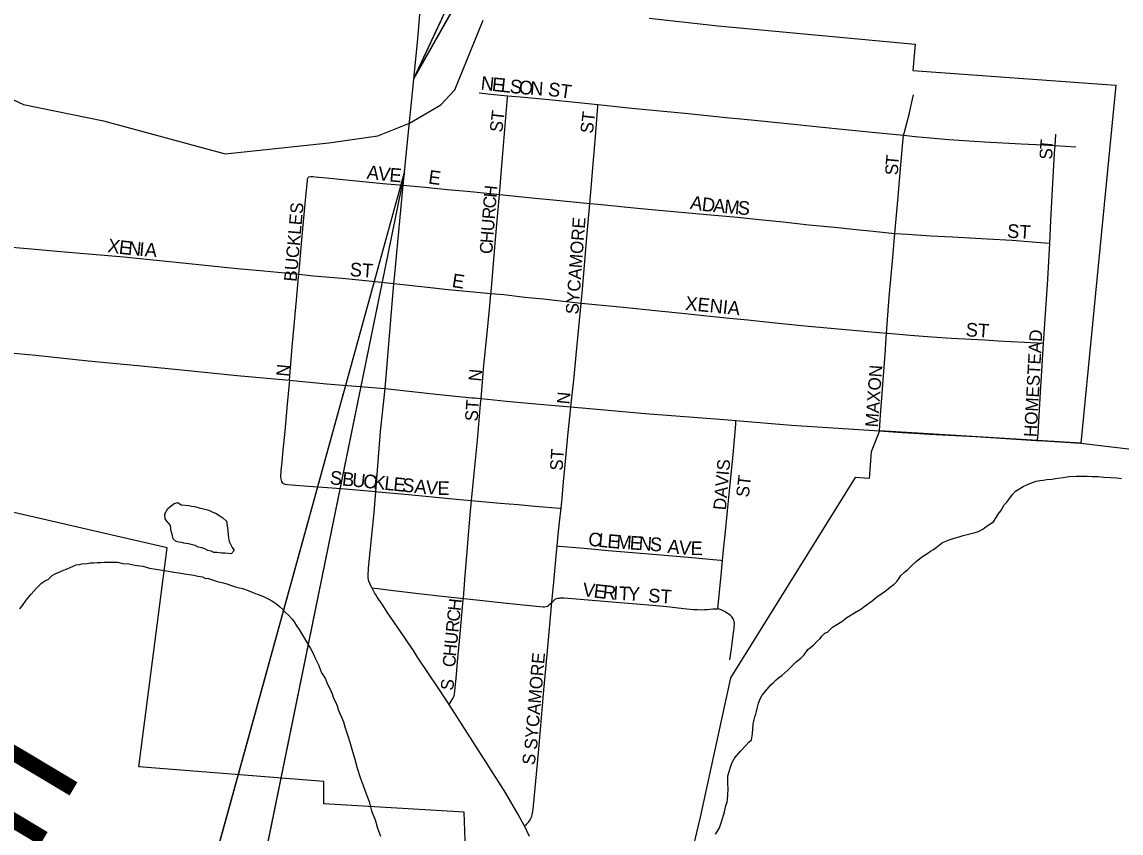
# Model space of a CAD drawing. Extents: x -13.9 to 69.1, y -25.2 to 26.1.
# Drawn here: x 3.981 to 4.71, y 17.455 to 17.993 of the extents above; entities that cross this region are included whole.
import ezdxf

# ---------------------------------------------------------------- set-up
doc = ezdxf.new("R2010")
doc.units = 0
for name, color, linetype in [('GM_X_City_Street', 7, 'Continuous'), ('GM_X_City_Street_Text', 7, 'Continuous'), ('GM_X_Corporation', 7, 'Continuous'), ('GM_X_Major_River', 7, 'Continuous'), ('GM_X_Minor_Lake', 7, 'Continuous'), ('GM_X_Minor_River', 7, 'Continuous'), ('GM_X_Minor_River_Text', 7, 'Continuous'), ('GM_X_State_Route', 7, 'Continuous'), ('SH_Text', 7, 'Continuous')]:
    doc.layers.add(name, color=color, linetype=linetype)

msp = doc.modelspace()

# ---------------------------------------------------------------- linework, layer by layer
at = {"layer": 'GM_X_City_Street'}
for points in [[(4.28452, 17.94603), (4.29432, 17.94511), (4.30348, 17.94424)], [(4.29797, 17.87876), (4.29973, 17.9005), (4.30339, 17.94304), (4.30348, 17.94424)], [(4.30348, 17.94424), (4.3145, 17.9432), (4.3354, 17.94119), (4.36326, 17.93837)], [(4.56601, 17.91796), (4.56654, 17.92013), (4.56819, 17.92613), (4.56967, 17.93173), (4.57085, 17.93704), (4.57251, 17.94487)], [(4.35791, 17.87281), (4.35887, 17.88294), (4.3602, 17.89913), (4.36166, 17.91696), (4.36318, 17.93723), (4.36326, 17.93837)], [(4.36326, 17.93837), (4.3859, 17.93607), (4.42091, 17.93272), (4.45053, 17.92965), (4.45809, 17.92889), (4.46946, 17.92778), (4.49323, 17.92528), (4.50999, 17.92352), (4.52746, 17.92186), (4.54296, 17.92038), (4.56601, 17.91796)], [(4.56031, 17.85291), (4.56213, 17.87471), (4.56417, 17.89849), (4.56544, 17.91328), (4.56601, 17.91796)], [(4.56601, 17.91796), (4.57367, 17.91716), (4.59601, 17.91514), (4.61974, 17.91373), (4.64409, 17.91238), (4.65881, 17.91156), (4.66644, 17.91113)], [(4.66644, 17.91113), (4.66669, 17.91455), (4.66699, 17.91865)], [(4.6629, 17.84642), (4.66369, 17.8615), (4.66458, 17.87814), (4.66608, 17.90624), (4.66644, 17.91113)], [(4.66644, 17.91113), (4.68017, 17.91037)], [(4.16497, 17.82582), (4.16559, 17.83265), (4.16682, 17.84626), (4.16785, 17.85831), (4.16994, 17.87968), (4.17067, 17.88768), (4.17082, 17.8891), (4.17101, 17.8896), (4.17118, 17.88997), (4.17166, 17.89036), (4.1729, 17.89059), (4.17436, 17.89063), (4.17586, 17.89051), (4.18332, 17.88978), (4.19854, 17.88828), (4.21405, 17.88675), (4.22073, 17.88611), (4.22885, 17.88533), (4.23425, 17.88481)], [(4.23425, 17.88481), (4.24876, 17.88363), (4.26338, 17.88212), (4.27658, 17.88083), (4.29412, 17.87915), (4.29797, 17.87876)], [(4.29242, 17.81314), (4.29249, 17.81401), (4.29429, 17.83554), (4.29543, 17.84878), (4.29695, 17.86625), (4.29797, 17.87876)], [(4.29797, 17.87876), (4.32161, 17.87639), (4.33358, 17.87521), (4.35791, 17.87281)], [(4.35232, 17.80677), (4.35285, 17.81324), (4.35615, 17.85288), (4.35742, 17.86766), (4.35791, 17.87281)], [(4.35791, 17.87281), (4.36332, 17.87228), (4.39186, 17.86947), (4.43302, 17.86576), (4.45598, 17.86369), (4.4703, 17.86218), (4.48611, 17.86051), (4.5032, 17.85871), (4.52011, 17.85702), (4.53453, 17.85555), (4.54592, 17.8544), (4.56031, 17.85291)], [(4.55478, 17.78675), (4.55653, 17.81075), (4.55878, 17.83443), (4.56031, 17.85291)], [(4.56031, 17.85291), (4.56868, 17.85236), (4.58413, 17.85142), (4.59837, 17.85062), (4.62154, 17.84933), (4.63799, 17.84841), (4.65385, 17.84701), (4.6629, 17.84642)], [(3.96097, 17.84498), (3.98006, 17.84336), (3.99255, 17.84228), (4.00966, 17.84081), (4.04898, 17.83743), (4.08147, 17.83411), (4.1242, 17.82975), (4.14183, 17.82805), (4.16497, 17.82582)], [(4.65891, 17.78016), (4.66016, 17.7995), (4.66164, 17.82247), (4.6629, 17.84642)], [(4.15879, 17.75552), (4.16066, 17.77774), (4.16221, 17.79422), (4.16263, 17.79946), (4.16342, 17.80876), (4.1648, 17.82391), (4.16497, 17.82582)], [(4.16497, 17.82582), (4.17476, 17.82488), (4.19383, 17.82315), (4.21147, 17.82152), (4.22809, 17.81972)], [(4.22809, 17.81972), (4.25037, 17.81719), (4.26393, 17.81569), (4.27102, 17.81511), (4.29242, 17.81314)], [(4.28587, 17.74337), (4.28773, 17.76547), (4.2896, 17.78458), (4.29159, 17.80492), (4.29242, 17.81314)], [(4.29242, 17.81314), (4.30097, 17.81235), (4.31489, 17.81074), (4.32699, 17.80946), (4.35232, 17.80677)], [(4.34536, 17.73786), (4.34751, 17.75787), (4.34891, 17.77215), (4.35025, 17.78595), (4.35232, 17.80677)], [(4.35232, 17.80677), (4.36395, 17.80554), (4.38014, 17.80399), (4.4015, 17.8019), (4.42113, 17.79987), (4.43563, 17.79836), (4.45051, 17.79682), (4.4628, 17.79554), (4.47877, 17.79388), (4.50053, 17.79162), (4.53738, 17.78827), (4.55478, 17.78675)], [(4.55009, 17.72192), (4.55074, 17.73251), (4.55377, 17.77283), (4.55478, 17.78675)], [(4.55478, 17.78675), (4.55553, 17.78668), (4.5704, 17.7854), (4.5847, 17.78426), (4.5979, 17.78351), (4.61994, 17.78239), (4.62875, 17.78173), (4.65468, 17.78038), (4.65891, 17.78016)], [(3.95538, 17.77564), (3.97146, 17.77403), (3.99066, 17.77209), (4.02531, 17.76854), (4.05827, 17.76524), (4.09169, 17.76208), (4.12413, 17.75877), (4.15879, 17.75552)], [(4.65485, 17.71566), (4.65516, 17.72058), (4.65692, 17.74772), (4.65793, 17.76516), (4.65891, 17.78016)], [(4.15879, 17.75552), (4.15859, 17.75349), (4.15729, 17.73962), (4.15565, 17.72177), (4.15441, 17.7092), (4.15366, 17.70153), (4.15316, 17.69561), (4.15294, 17.69146), (4.15302, 17.69011), (4.15317, 17.6892), (4.15353, 17.68842), (4.15397, 17.68783), (4.15452, 17.68728), (4.15518, 17.68689), (4.15602, 17.68665), (4.15745, 17.68646), (4.16272, 17.68606), (4.17146, 17.68542), (4.18083, 17.68474), (4.19311, 17.68386), (4.21606, 17.68175)], [(4.15879, 17.75552), (4.18329, 17.75323), (4.22219, 17.75004)], [(4.27948, 17.67578), (4.28129, 17.69379), (4.2835, 17.71586), (4.28555, 17.73971), (4.28587, 17.74337)], [(4.33887, 17.67068), (4.33961, 17.67742), (4.34056, 17.68812), (4.342, 17.70407), (4.34332, 17.71872), (4.3451, 17.73546), (4.34536, 17.73786)], [(4.44597, 17.63606), (4.44693, 17.64524), (4.44773, 17.65313), (4.44925, 17.66907), (4.45071, 17.68442), (4.45299, 17.70604), (4.45468, 17.72634), (4.45488, 17.7288)], [(4.21606, 17.68175), (4.2177, 17.6816), (4.23311, 17.68034), (4.25584, 17.67804), (4.27178, 17.67643), (4.27948, 17.67578)], [(4.27414, 17.61081), (4.27518, 17.62351), (4.27868, 17.66624), (4.27948, 17.67578)], [(4.27948, 17.67578), (4.28645, 17.67517), (4.29856, 17.67413), (4.3104, 17.67312), (4.32146, 17.67218), (4.33813, 17.67076), (4.33887, 17.67068)], [(4.33634, 17.64573), (4.33704, 17.65298), (4.33786, 17.66149), (4.33887, 17.67068)], [(4.33269, 17.60831), (4.3331, 17.6128), (4.33402, 17.62165), (4.33568, 17.63888), (4.33634, 17.64573)], [(4.33634, 17.64573), (4.33773, 17.6456), (4.35415, 17.64416), (4.37007, 17.64277), (4.39985, 17.64016), (4.42315, 17.63816), (4.4447, 17.63618), (4.44597, 17.63606)], [(4.4428, 17.6041), (4.44496, 17.62636), (4.44597, 17.63606)], [(4.21339, 17.618), (4.21745, 17.61748), (4.22786, 17.61618), (4.2443, 17.61424), (4.26001, 17.61238), (4.27414, 17.61081)], [(4.26458, 17.54047), (4.26609, 17.5428), (4.26719, 17.5445), (4.26765, 17.54552), (4.26798, 17.54663), (4.26812, 17.54761), (4.26927, 17.55788), (4.27027, 17.56883), (4.27197, 17.58737), (4.27407, 17.61004), (4.27414, 17.61081)], [(4.27414, 17.61081), (4.28504, 17.60965), (4.29679, 17.60841), (4.31382, 17.60661), (4.32704, 17.60523), (4.32801, 17.60529), (4.32906, 17.60549), (4.32987, 17.60576), (4.33063, 17.6063), (4.3314, 17.60706), (4.33269, 17.6083), (4.33269, 17.60831)], [(4.31456, 17.46016), (4.31587, 17.46132), (4.31728, 17.4626), (4.31808, 17.46366), (4.31857, 17.46449), (4.31912, 17.46563), (4.31941, 17.46646), (4.31971, 17.46732), (4.31993, 17.4685), (4.32011, 17.4696), (4.32038, 17.47132), (4.32063, 17.47341), (4.32222, 17.4897), (4.32384, 17.50844), (4.32539, 17.52641), (4.32734, 17.54772), (4.3298, 17.57613), (4.33269, 17.60831)], [(4.33269, 17.60831), (4.33364, 17.60915), (4.33432, 17.60984), (4.33499, 17.61042), (4.33575, 17.61078), (4.33682, 17.61106), (4.33774, 17.61117), (4.33855, 17.61123), (4.33951, 17.61123), (4.34065, 17.6112), (4.34896, 17.61059), (4.3728, 17.60864), (4.39693, 17.60667), (4.40904, 17.60554), (4.42223, 17.6041), (4.42661, 17.60362), (4.42946, 17.60345), (4.43207, 17.60337), (4.43395, 17.60348), (4.4359, 17.60356), (4.43757, 17.60378), (4.43946, 17.60395), (4.44104, 17.6041), (4.4428, 17.6041)], [(4.45091, 17.57023), (4.45191, 17.57745), (4.45334, 17.58822), (4.45363, 17.59105), (4.45377, 17.59232), (4.45384, 17.59357), (4.45387, 17.59455), (4.45365, 17.59569), (4.45343, 17.59644), (4.45304, 17.59733), (4.45265, 17.59804), (4.4521, 17.59879), (4.4513, 17.59967), (4.45047, 17.60033), (4.44985, 17.60076), (4.44912, 17.60119), (4.44719, 17.60225), (4.4456, 17.60301), (4.44405, 17.60367), (4.4428, 17.6041)]]:
    msp.add_lwpolyline(points, dxfattribs=at)
at = {"layer": 'GM_X_Corporation'}
for points in [[(4.39727, 17.99575), (4.44305, 17.99067), (4.57374, 17.97833), (4.57208, 17.96095), (4.70688, 17.95124), (4.68348, 17.71385), (4.65485, 17.71566), (4.55009, 17.72192), (4.5445, 17.70802), (4.54315, 17.6904), (4.53402, 17.69118), (4.45123, 17.55819), (4.43114, 17.46595), (4.42416, 17.43621)], [(4.27723, 17.39488), (4.27455, 17.46918), (4.18168, 17.47477), (4.18168, 17.48942), (4.05882, 17.49916), (4.0776, 17.64436), (3.89621, 17.68632)]]:
    msp.add_lwpolyline(points, dxfattribs=at)
at = {"layer": 'GM_X_Major_River'}
msp.add_lwpolyline([(3.83078, 17.9959), (3.87742, 17.98798), (3.88715, 17.98632), (3.91888, 17.97364), (3.94781, 17.95447), (3.98252, 17.93846), (4.03549, 17.92749), (4.11619, 17.90574), (4.18499, 17.91296), (4.21738, 17.91771), (4.2384, 17.92597), (4.25916, 17.93823), (4.26844, 17.9482), (4.28713, 17.9943)], dxfattribs=at)
at = {"layer": 'GM_X_Minor_Lake'}
msp.add_lwpolyline([(4.07615, 17.66692), (4.07821, 17.67053), (4.08229, 17.67375), (4.08466, 17.67445), (4.08701, 17.67297), (4.09207, 17.67254), (4.09375, 17.67216), (4.09611, 17.67177), (4.09881, 17.67101), (4.10184, 17.67024), (4.10352, 17.66986), (4.10521, 17.66948), (4.10756, 17.66836), (4.11025, 17.66723), (4.1126, 17.66575), (4.11461, 17.66427), (4.11695, 17.66206), (4.1179, 17.65587), (4.1182, 17.65259), (4.11884, 17.64858), (4.12082, 17.64456), (4.12216, 17.64272), (4.12011, 17.64056), (4.11606, 17.64098), (4.1137, 17.64101), (4.11067, 17.64141), (4.10864, 17.64143), (4.10696, 17.64218), (4.1046, 17.64257), (4.10259, 17.64369), (4.10057, 17.64444), (4.09821, 17.64483), (4.0962, 17.64595), (4.0935, 17.64671), (4.09182, 17.64709), (4.08879, 17.64749), (4.0871, 17.64788), (4.08542, 17.64826), (4.08373, 17.64864), (4.08173, 17.65049), (4.08108, 17.6534), (4.08042, 17.65523), (4.07979, 17.65924), (4.07779, 17.66181), (4.07646, 17.66364), (4.07614, 17.66619), (4.07615, 17.66692), (4.07615, 17.66655)], dxfattribs=at)
at = {"layer": 'GM_X_Minor_River'}
for points in [[(4.6359, 17.67651), (4.63829, 17.67975), (4.64034, 17.68191), (4.64543, 17.68512), (4.64815, 17.68654), (4.65086, 17.6876), (4.65391, 17.68865), (4.65627, 17.68899), (4.65864, 17.68932), (4.661, 17.68966), (4.66438, 17.68998), (4.6681, 17.69066), (4.67182, 17.69098), (4.67587, 17.69166), (4.6806, 17.69197), (4.68432, 17.69192), (4.68769, 17.69188), (4.69107, 17.69184), (4.69478, 17.6918), (4.69883, 17.69138), (4.70321, 17.69097), (4.70726, 17.69092), (4.71063, 17.69051)], [(4.44131, 17.45448), (4.44268, 17.45664), (4.44405, 17.45881), (4.44509, 17.46207), (4.44614, 17.46569), (4.44719, 17.46931), (4.44825, 17.47367), (4.44894, 17.47584), (4.4493, 17.47765), (4.4497, 17.4842), (4.44941, 17.48856), (4.44945, 17.49329), (4.4505, 17.49691), (4.4512, 17.49909), (4.45223, 17.50162), (4.45395, 17.50487), (4.45806, 17.50991), (4.46113, 17.51315), (4.46351, 17.51567), (4.46521, 17.5171), (4.46593, 17.52109), (4.46633, 17.52763), (4.46703, 17.53054), (4.46739, 17.53235), (4.46808, 17.53416), (4.46844, 17.53597), (4.46914, 17.53887), (4.46984, 17.54141), (4.47122, 17.54467), (4.47226, 17.54684), (4.47806, 17.55368), (4.47976, 17.55511), (4.48147, 17.55691), (4.48317, 17.55834), (4.48521, 17.55977), (4.48725, 17.56157), (4.4893, 17.56336), (4.49203, 17.56624), (4.49475, 17.56875), (4.49781, 17.57126), (4.5002, 17.57341), (4.5026, 17.57702), (4.50634, 17.57988), (4.50839, 17.5824), (4.51043, 17.5842), (4.51214, 17.58599), (4.51384, 17.58779), (4.51554, 17.5885), (4.51894, 17.59173), (4.52166, 17.59352), (4.52506, 17.59566), (4.52846, 17.59816), (4.53355, 17.60137), (4.53763, 17.60387), (4.54137, 17.60673), (4.54511, 17.60923), (4.54817, 17.61174), (4.55157, 17.61425), (4.55463, 17.61639), (4.55735, 17.61854), (4.55973, 17.62033), (4.56144, 17.62213), (4.56281, 17.62393), (4.56418, 17.6261), (4.56656, 17.62825), (4.56894, 17.63004), (4.57133, 17.63256), (4.57439, 17.63543), (4.5778, 17.6383), (4.58153, 17.64043), (4.58391, 17.64222), (4.58595, 17.64329), (4.58765, 17.64472), (4.58969, 17.64615), (4.59173, 17.64795), (4.59614, 17.64971), (4.59953, 17.65076), (4.60291, 17.65181), (4.60562, 17.65251), (4.6134, 17.65459), (4.61577, 17.65529), (4.61849, 17.65671), (4.62086, 17.6585), (4.62392, 17.66065), (4.62562, 17.66172), (4.62871, 17.66677), (4.63042, 17.66894), (4.63282, 17.67291), (4.63453, 17.6747), (4.6359, 17.67651)], [(3.98001, 17.60408), (3.98171, 17.60624), (3.98411, 17.60985), (3.98753, 17.6138), (3.99094, 17.61776), (3.99435, 17.621), (3.99707, 17.62278), (3.99876, 17.62349), (4.00149, 17.626), (4.00387, 17.62743), (4.00658, 17.62849), (4.00895, 17.62955), (4.01132, 17.63061), (4.01336, 17.63131), (4.01539, 17.63238), (4.01742, 17.63308), (4.01945, 17.63342), (4.02114, 17.63376), (4.02452, 17.63409), (4.02689, 17.63442), (4.02891, 17.6344), (4.03128, 17.63473), (4.03364, 17.6347), (4.03601, 17.63504), (4.03871, 17.635), (4.04141, 17.63497), (4.04478, 17.63493), (4.04815, 17.63416), (4.0522, 17.63375), (4.05624, 17.63297), (4.06163, 17.63218), (4.06601, 17.63104), (4.07848, 17.62907), (4.08218, 17.6283), (4.08555, 17.62789), (4.08926, 17.62712), (4.09229, 17.62672), (4.09533, 17.62632), (4.09802, 17.62556), (4.10106, 17.62516), (4.10274, 17.62441), (4.1051, 17.62402), (4.10779, 17.62326), (4.11082, 17.62213), (4.11384, 17.62137), (4.11721, 17.6206), (4.12024, 17.61947), (4.1236, 17.61834), (4.12765, 17.61756), (4.13134, 17.61606), (4.13403, 17.61494), (4.1374, 17.61381), (4.14043, 17.61268), (4.14278, 17.61156), (4.14513, 17.61044), (4.14714, 17.60933), (4.14882, 17.60821), (4.1505, 17.6071), (4.15217, 17.60563), (4.15418, 17.60379), (4.15618, 17.60158), (4.15819, 17.59974), (4.16053, 17.59716), (4.16186, 17.59533), (4.16352, 17.59276), (4.16518, 17.5902), (4.16684, 17.58763), (4.16884, 17.58433), (4.17083, 17.58104), (4.17282, 17.57774), (4.17448, 17.57445), (4.17613, 17.57079), (4.17812, 17.56676), (4.18009, 17.56165), (4.18242, 17.55798), (4.18406, 17.55396), (4.18572, 17.55067), (4.18704, 17.54774), (4.18802, 17.54482), (4.18935, 17.54226), (4.19034, 17.53971), (4.19099, 17.53715), (4.19462, 17.52911), (4.1956, 17.52582), (4.19658, 17.52254), (4.19789, 17.51852), (4.1992, 17.51414)], [(4.1992, 17.51414), (4.2005, 17.5094), (4.20214, 17.50429), (4.20377, 17.49845), (4.20573, 17.49224), (4.20771, 17.48676), (4.20968, 17.48128), (4.21165, 17.47617), (4.21328, 17.46997), (4.21558, 17.46412), (4.21722, 17.45864), (4.21919, 17.45316)]]:
    msp.add_lwpolyline(points, dxfattribs=at)
at = {"layer": 'GM_X_State_Route'}
for points in [[(4.22837, 17.8235), (4.22856, 17.82598), (4.23191, 17.86127), (4.23425, 17.88481), (4.24364, 17.97953), (4.24496, 17.99521), (4.24541, 18.00202), (4.24556, 18.00538), (4.24504, 18.01336), (4.24471, 18.01632)], [(4.22219, 17.75004), (4.22591, 17.79568), (4.22809, 17.81972), (4.22837, 17.8235)], [(4.21123, 17.63095), (4.21498, 17.66792), (4.21606, 17.68175), (4.21918, 17.72167), (4.22219, 17.75004)], [(4.22219, 17.75004), (4.25599, 17.74644), (4.27961, 17.744), (4.28145, 17.74382)], [(4.28145, 17.74382), (4.28587, 17.74337), (4.3027, 17.7417), (4.32457, 17.73965), (4.34536, 17.73786), (4.37008, 17.73573)], [(4.37008, 17.73573), (4.39464, 17.73361), (4.44699, 17.72943), (4.45488, 17.7288), (4.49161, 17.72583), (4.55009, 17.72192)], [(4.55009, 17.72192), (4.56518, 17.72093)], [(4.56518, 17.72093), (4.57661, 17.72018), (4.58293, 17.71984)], [(4.58293, 17.71984), (4.61365, 17.71817), (4.65396, 17.71571)], [(4.65396, 17.71571), (4.65485, 17.71566), (4.65565, 17.71561), (4.68348, 17.71385), (4.70761, 17.71107), (4.76256, 17.7046), (4.79333, 17.70096), (4.81859, 17.69772), (4.83941, 17.69466), (4.85055, 17.69303), (4.85748, 17.69134), (4.86441, 17.68931), (4.87087, 17.68693), (4.87607, 17.68473), (4.88048, 17.68269), (4.88474, 17.68049), (4.88821, 17.67846)], [(4.31799, 17.45301), (4.31456, 17.46016), (4.31442, 17.46044), (4.31049, 17.46764), (4.30223, 17.48176), (4.29089, 17.49937), (4.27694, 17.5215), (4.26458, 17.54047), (4.25729, 17.55167), (4.24374, 17.5719), (4.24094, 17.57626), (4.23744, 17.58153), (4.2353, 17.58475), (4.2285, 17.59472), (4.22363, 17.60182), (4.22015, 17.60699), (4.21701, 17.61177), (4.21583, 17.61373), (4.21523, 17.6147), (4.21353, 17.61771), (4.21339, 17.618), (4.21224, 17.62028), (4.21143, 17.62234), (4.21119, 17.6233), (4.21101, 17.62481), (4.21105, 17.62706), (4.21115, 17.63011), (4.21123, 17.63095)]]:
    msp.add_lwpolyline(points, dxfattribs=at)
at = {"layer": 'SH_Text'}
for p, q in [((4.24126, 17.95556), (5.00728, 19.59434)), ((5.00728, 19.31171), (4.24126, 17.95556)), ((3.98257, 16.97889), (4.23509, 17.89335)), ((4.23509, 17.89335), (3.98257, 16.65677))]:
    msp.add_line(p, q, dxfattribs=at)
for points in [[(5.00728, 19.59434), (4.24126, 17.95556), (5.00728, 19.31171)], [(3.98257, 16.97889), (4.23509, 17.89335), (3.98257, 16.65677)]]:
    msp.add_lwpolyline(points, close=True, dxfattribs=at)

# ---------------------------------------------------------------- texts
at = {"layer": 'GM_X_City_Street_Text'}
for s, height, rotation, p in [('N', 0.00906, 353.87782, (4.28533, 17.94826)), ('E', 0.00906, 353.87957, (4.2927, 17.94747)), ('L', 0.00906, 353.85037, (4.2986, 17.94684)), ('S', 0.00906, 353.87123, (4.30451, 17.9462)), ('O', 0.00906, 354.77194, (4.31055, 17.94555)), ('N', 0.00906, 356.1041, (4.31813, 17.94486)), ('ST', 0.009054, 352.34575, (4.32984, 17.94427)), ('ST', 0.008435, 83.37616, (4.2999, 17.91966)), ('ST', 0.008435, 83.37616, (4.35996, 17.91886)), ('T', 0.00843, 84.68231, (4.66473, 17.90804)), ('S', 0.00842, 89.11124, (4.66464, 17.90186)), ('T', 0.00843, 84.63172, (4.56244, 17.89767)), ('A', 0.00906, 353.14662, (4.20974, 17.88923)), ('V', 0.00906, 353.14662, (4.21711, 17.88835)), ('E', 0.00906, 355.06963, (4.22476, 17.88744)), ('E', 0.00905, 352.34395, (4.25052, 17.88604)), ('S', 0.00842, 88.95891, (4.56233, 17.89148)), ('H', 0.00843, 84.3802, (4.29604, 17.87633)), ('A', 0.00905, 350.33062, (4.42408, 17.86928)), ('BUCKLES', 0.00843, 84.90665, (4.16349, 17.82066)), ('C', 0.00843, 85.68359, (4.2955, 17.86923)), ('D', 0.00906, 353.58441, (4.43189, 17.86796)), ('A', 0.00906, 354.85715, (4.43945, 17.86711)), ('M', 0.00906, 354.89202, (4.44684, 17.86644)), ('S', 0.00906, 354.89486, (4.45571, 17.86565)), ('R', 0.00843, 85.69056, (4.29496, 17.86208)), ('SYCAMORE', 0.008429, 85.67496, (4.3503, 17.79904)), ('U', 0.00843, 85.68756, (4.29436, 17.85413)), ('ST', 0.009061, 356.15481, (4.63444, 17.85016)), ('X', 0.00905, 351.94175, (4.03777, 17.84057)), ('H', 0.00843, 85.6797, (4.29376, 17.84617)), ('E', 0.00906, 353.25435, (4.04532, 17.83951)), ('N', 0.00906, 355.00214, (4.05147, 17.83878)), ('I', 0.00906, 355.10669, (4.05888, 17.83814)), ('A', 0.00906, 355.14718, (4.06258, 17.83782)), ('C', 0.00843, 85.68359, (4.29322, 17.83902)), ('ST', 0.009061, 356.15481, (4.19853, 17.82463)), ('E', 0.00905, 351.26665, (4.26612, 17.81744)), ('XENIA', 0.009058, 354.2076, (4.42099, 17.80229)), ('ST', 0.009061, 356.15573, (4.60701, 17.78475)), ('HOMESTEAD', 0.008427, 86.90665, (4.65426, 17.71771)), ('N', 0.00843, 84.67177, (4.1583, 17.7577)), ('N', 0.00843, 84.69192, (4.28581, 17.75451)), ('MAXON', 0.008428, 85.90904, (4.54899, 17.72415)), ('N', 0.00843, 84.69393, (4.34438, 17.73935)), ('ST', 0.008427, 86.45609, (4.28359, 17.72813)), ('ST', 0.008427, 86.67776, (4.33993, 17.69542)), ('DAVIS', 0.00843, 84.94416, (4.44817, 17.66915)), ('S', 0.00906, 354.20374, (4.18524, 17.68664)), ('B', 0.00906, 354.19471, (4.19335, 17.68582)), ('U', 0.00906, 354.20958, (4.2, 17.68514)), ('C', 0.00906, 354.194, (4.20738, 17.68439)), ('K', 0.00906, 354.19092, (4.21402, 17.68372)), ('L', 0.00906, 354.19836, (4.2214, 17.68297)), ('E', 0.00906, 354.20374, (4.22731, 17.68237)), ('S', 0.00906, 354.20374, (4.23321, 17.68177)), ('A', 0.00906, 354.20222, (4.24133, 17.68094)), ('V', 0.00906, 355.39006, (4.24889, 17.68018)), ('E', 0.00906, 359.2248, (4.25686, 17.67955)), ('ST', 0.008435, 83.37772, (4.4633, 17.67764)), ('C', 0.00906, 353.59183, (4.35651, 17.64596)), ('L', 0.00906, 353.80269, (4.36317, 17.64521)), ('E', 0.00906, 355.22215, (4.36929, 17.64455)), ('M', 0.00906, 356.04886, (4.37533, 17.64404)), ('E', 0.00906, 356.05953, (4.3842, 17.64343)), ('N', 0.00906, 356.06821, (4.39013, 17.64302)), ('S', 0.00906, 356.06704, (4.39752, 17.64251)), ('A', 0.00906, 353.66759, (4.40914, 17.64117)), ('V', 0.00906, 355.07465, (4.41673, 17.64034)), ('E', 0.00906, 359.2248, (4.42474, 17.63967)), ('V', 0.00906, 353.24252, (4.35281, 17.61246)), ('E', 0.00906, 353.2315, (4.36018, 17.61158)), ('R', 0.00906, 353.95987, (4.36618, 17.61087)), ('I', 0.00906, 356.45597, (4.37319, 17.61014)), ('T', 0.00906, 357.39018, (4.37703, 17.6099)), ('Y', 0.00906, 357.5056, (4.38297, 17.60963)), ('ST', 0.009061, 356.15573, (4.39647, 17.60848)), ('H', 0.00843, 84.09503, (4.27224, 17.60233)), ('C', 0.00843, 84.09386, (4.2715, 17.59519)), ('R', 0.00843, 84.09927, (4.27077, 17.58806)), ('U', 0.00843, 84.09261, (4.26995, 17.58013)), ('H', 0.00843, 84.35998, (4.26916, 17.57221)), ('C', 0.00843, 86.63454, (4.26875, 17.56515)), ('SYCAMORE', 0.00843, 85.16977, (4.32288, 17.51039)), ('S', 0.00843, 83.37616, (4.26728, 17.54956)), ('S', 0.00843, 83.37616, (4.3214, 17.50011))]:
    msp.add_text(s, height=height, rotation=rotation, dxfattribs=at).set_placement(p)
at = {"layer": 'GM_X_Minor_River_Text'}
msp.add_text('Branch', height=0.086138, rotation=59.14304, dxfattribs=at).set_placement((3.83482, 17.18212))

doc.saveas('drawing.dxf')
